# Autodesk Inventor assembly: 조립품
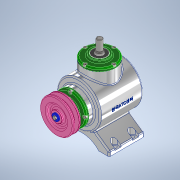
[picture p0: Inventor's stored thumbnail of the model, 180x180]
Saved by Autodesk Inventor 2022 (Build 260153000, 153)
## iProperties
Created: 2023-04
Part Number: 조립품
Document SubType Name: Assembly
Designer: Admin
Author: Admin
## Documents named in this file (17)
- C:\Users\Admin\Desktop\730411V1006\조립품.iam
- C:\Users\Admin\Desktop\730411V1006\본체.ipt
- C:\Users\Admin\Desktop\730411V1006\커버.ipt
- C:\Users\Admin\Desktop\730411V1006\베어링 6203.ipt
- C:\Users\Admin\Desktop\730411V1006\오일실 17 x 32 x 8.ipt
- C:\Users\Admin\Desktop\730411V1006\메인 축.ipt
- 메인 축.ipt
- C:\Users\Admin\Desktop\730411V1006\Ű 5 x 5 x 14.ipt
- C:\Users\Admin\Desktop\730411V1006\메인 베벨기어.ipt
- C:\Users\Admin\Desktop\730411V1006\서브 축.ipt
- 서브 축.ipt
- C:\Users\Admin\Desktop\730411V1006\Ű 4 x 4 x 14.ipt
- C:\Users\Admin\Desktop\730411V1006\서브 베벨기어.ipt
- C:\Users\Admin\Desktop\730411V1006\V-벨트풀리.ipt
- C:\Users\Admin\Desktop\730411V1006\볼트 M4 x 10.ipt
- C:\Users\Admin\Desktop\730411V1006\와셔 4 x 16.ipt
- C:\Users\Admin\Desktop\730411V1006\육각볼트 M4 x 8.ipt
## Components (4 placed, 3 different names)
1. Ű 5 x 5 x 14:1
2. Ű 4 x 4 x 14:1
3. Ű 4 x 4 x 14:2
4. V-벨트풀리:1
